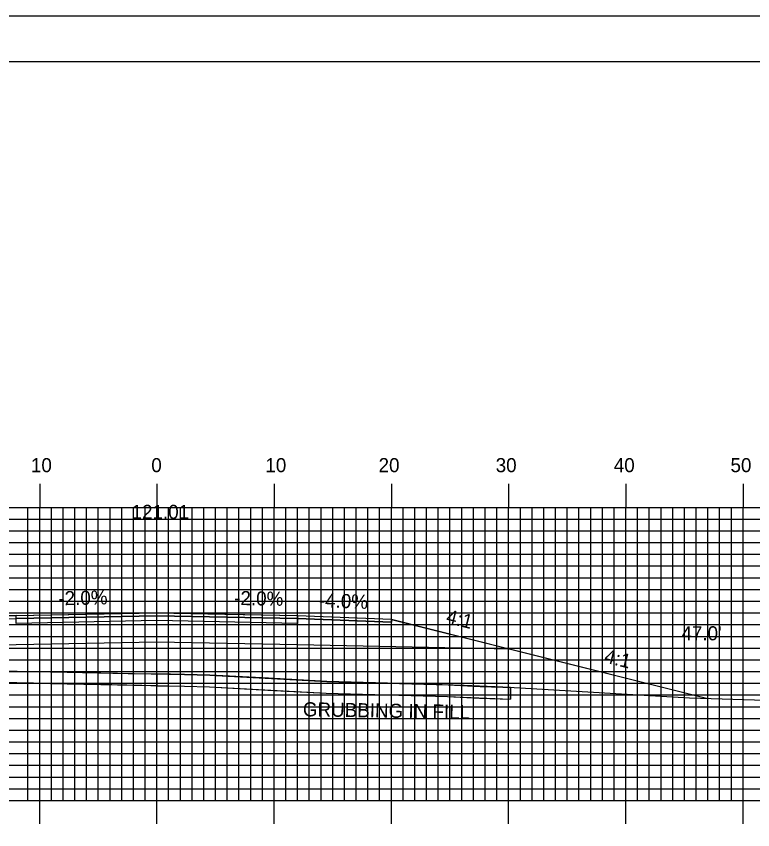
# Model space of a CAD drawing. Extents: x 1772022 to 1772366, y 442591 to 442811.
# Drawn here: x 1772176.1 to 1772238.9, y 442741.2 to 442810.5 of the extents above; entities that cross this region are included whole.
import ezdxf

# ---------------------------------------------------------------- set-up
doc = ezdxf.new("R2010")
doc.units = 0
for name, color, linetype in [('ANNOTATION', 7, 'Continuous'), ('BORDER', 7, 'Continuous'), ('D_Roadway_Centerline', 7, 'Continuous'), ('D_Roadway_Centerline_Text', 7, 'Continuous'), ('D_Roadway_Edge_Shoulder', 7, 'Continuous'), ('D_Roadway_Edge_TW', 7, 'Continuous'), ('D_Roadway_Pavement', 7, 'Continuous'), ('D_Roadway_SlopeLines', 7, 'Continuous'), ('D_Roadway_SubGrade', 7, 'Continuous'), ('D_Text_Standard', 7, 'Continuous'), ('GRUBBING IN FILL', 7, 'Continuous'), ('H_V ANNOTATION', 7, 'Continuous'), ('MAJOR', 7, 'Continuous'), ('MINOR', 7, 'Continuous'), ('PLOT BOUNDARY', 7, 'Continuous'), ('S_Roadway_Centerline', 7, 'Continuous')]:
    doc.layers.add(name, color=color, linetype=linetype)

msp = doc.modelspace()

# ---------------------------------------------------------------- linework, layer by layer
at = {"layer": 'BORDER'}
msp.add_lwpolyline([(1772038.494, 442596.665), (1772358.494, 442596.665), (1772358.494, 442806.665), (1772038.494, 442806.665)], close=True, dxfattribs=at)
at = {"layer": 'D_Roadway_Centerline'}
msp.add_lwpolyline([(1772154.321, 442755.673), (1772155.067, 442755.86), (1772156.093, 442756.116), (1772157.021, 442756.348), (1772157.919, 442756.572), (1772168.091, 442759.116), (1772168.093, 442759.116), (1772168.095, 442759.116), (1772176.094, 442759.436), (1772183.479, 442759.584), (1772188.09, 442759.676), (1772188.093, 442759.676), (1772193.883, 442759.56), (1772200.09, 442759.436), (1772200.093, 442759.436), (1772200.095, 442759.436), (1772208.094, 442759.116), (1772208.097, 442759.115), (1772218.268, 442756.572), (1772218.274, 442756.571), (1772235.086, 442752.368)], dxfattribs=at)
at = {"layer": 'D_Roadway_Edge_Shoulder'}
for points in [[(1772176.094, 442759.436), (1772168.093, 442759.116), (1772168.093, 442758.866), (1772176.094, 442759.186)], [(1772200.093, 442759.436), (1772208.094, 442759.116), (1772208.094, 442758.866), (1772200.093, 442759.186)]]:
    msp.add_lwpolyline(points, close=True, dxfattribs=at)
at = {"layer": 'D_Roadway_Edge_TW'}
msp.add_lwpolyline([(1772176.094, 442759.186), (1772176.094, 442759.436), (1772188.093, 442759.676), (1772200.093, 442759.436), (1772200.093, 442759.186), (1772188.093, 442759.426)], close=True, dxfattribs=at)
at = {"layer": 'D_Roadway_Pavement'}
msp.add_lwpolyline([(1772176.094, 442758.769), (1772176.094, 442759.186), (1772188.093, 442759.426), (1772200.093, 442759.186), (1772200.093, 442758.769), (1772188.093, 442759.009)], close=True, dxfattribs=at)
at = {"layer": 'D_Roadway_SlopeLines'}
msp.add_lwpolyline([(1772208.094, 442759.116), (1772218.268, 442756.572), (1772235.086, 442752.368)], dxfattribs=at)
at = {"layer": 'D_Roadway_SubGrade'}
msp.add_lwpolyline([(1772176.094, 442756.936), (1772157.919, 442756.572), (1772168.093, 442759.116), (1772168.093, 442758.866), (1772176.094, 442759.186), (1772188.093, 442759.426), (1772200.093, 442759.186), (1772208.094, 442758.866), (1772208.094, 442759.116), (1772218.268, 442756.572), (1772200.093, 442756.936), (1772188.093, 442757.176)], close=True, dxfattribs=at)
at = {"layer": 'GRUBBING IN FILL'}
msp.add_line((1772218.268, 442753.3), (1772218.268, 442752.3), dxfattribs=at)
msp.add_line((1772218.268, 442753.3), (1772218.268, 442752.3), dxfattribs=at)
for points in [[(1772157.919, 442755.405), (1772160.888, 442755.272), (1772165.211, 442755.078), (1772168.132, 442754.881), (1772170.426, 442754.81), (1772180.442, 442754.609), (1772185.641, 442754.505), (1772188.094, 442754.456), (1772188.094, 442753.455), (1772180.417, 442753.609), (1772170.4, 442753.81), (1772165.155, 442754.08), (1772157.919, 442754.404)], [(1772157.919, 442755.405), (1772160.888, 442755.272), (1772165.211, 442755.078), (1772168.132, 442754.881), (1772170.426, 442754.81), (1772180.442, 442754.609), (1772185.641, 442754.505), (1772188.094, 442754.456), (1772188.094, 442753.455), (1772180.417, 442753.609), (1772170.4, 442753.81), (1772165.155, 442754.08), (1772157.919, 442754.404)], [(1772188.094, 442753.455), (1772190.435, 442753.408), (1772192.574, 442753.345), (1772197.558, 442753.085), (1772202.543, 442752.825), (1772207.715, 442752.684), (1772212.888, 442752.544), (1772218.268, 442752.3), (1772218.268, 442753.3), (1772214.297, 442753.466), (1772207.756, 442753.684), (1772202.582, 442753.824), (1772197.598, 442754.084), (1772192.615, 442754.344), (1772190.459, 442754.408), (1772188.094, 442754.456)], [(1772188.094, 442753.455), (1772190.435, 442753.408), (1772192.574, 442753.345), (1772197.558, 442753.085), (1772202.543, 442752.825), (1772207.715, 442752.684), (1772212.888, 442752.544), (1772218.268, 442752.3), (1772218.268, 442753.3), (1772214.297, 442753.466), (1772207.756, 442753.684), (1772202.582, 442753.824), (1772197.598, 442754.084), (1772192.615, 442754.344), (1772190.459, 442754.408), (1772188.094, 442754.456)]]:
    msp.add_lwpolyline(points, close=True, dxfattribs=at)
msp.add_lwpolyline([(1772157.919, 442754.404), (1772165.155, 442754.08), (1772168.083, 442753.882), (1772170.4, 442753.81), (1772190.435, 442753.408), (1772192.574, 442753.345), (1772202.543, 442752.825), (1772212.888, 442752.544), (1772215.62, 442752.389), (1772218.268, 442752.3)], dxfattribs=at)
msp.add_lwpolyline([(1772157.919, 442754.404), (1772165.155, 442754.08), (1772168.083, 442753.882), (1772170.4, 442753.81), (1772190.435, 442753.408), (1772192.574, 442753.345), (1772202.543, 442752.825), (1772212.888, 442752.544), (1772215.62, 442752.389), (1772218.268, 442752.3)], dxfattribs=at)
at = {"layer": 'MAJOR'}
for p, q in [((1772178.094, 442770.669), (1772178.094, 442768.665)), ((1772188.094, 442770.669), (1772188.094, 442768.665)), ((1772198.094, 442770.669), (1772198.094, 442768.665)), ((1772208.094, 442770.669), (1772208.094, 442768.665)), ((1772218.094, 442770.669), (1772218.094, 442768.665)), ((1772228.094, 442770.669), (1772228.094, 442768.665)), ((1772238.094, 442770.669), (1772238.094, 442768.665)), ((1772048.094, 442768.665), (1772328.094, 442768.665)), ((1772048.094, 442768.665), (1772328.094, 442768.665)), ((1772178.094, 442743.665), (1772178.094, 442768.665)), ((1772188.094, 442743.665), (1772188.094, 442768.665)), ((1772198.094, 442743.665), (1772198.094, 442768.665)), ((1772208.094, 442743.665), (1772208.094, 442768.665)), ((1772218.094, 442743.665), (1772218.094, 442768.665)), ((1772228.094, 442743.665), (1772228.094, 442768.665)), ((1772238.094, 442743.665), (1772238.094, 442768.665)), ((1772048.094, 442763.665), (1772328.094, 442763.665)), ((1772048.094, 442758.665), (1772328.094, 442758.665)), ((1772048.094, 442753.665), (1772328.094, 442753.665)), ((1772048.094, 442748.665), (1772328.094, 442748.665)), ((1772048.094, 442743.665), (1772328.094, 442743.665)), ((1772048.094, 442743.665), (1772328.094, 442743.665)), ((1772178.094, 442741.661), (1772178.094, 442743.665)), ((1772188.094, 442741.661), (1772188.094, 442743.665)), ((1772198.094, 442741.661), (1772198.094, 442743.665)), ((1772208.094, 442741.661), (1772208.094, 442743.665)), ((1772218.094, 442741.661), (1772218.094, 442743.665)), ((1772228.094, 442741.661), (1772228.094, 442743.665)), ((1772238.094, 442741.661), (1772238.094, 442743.665))]:
    msp.add_line(p, q, dxfattribs=at)
at = {"layer": 'MINOR'}
for p, q in [((1772177.094, 442743.665), (1772177.094, 442768.665)), ((1772179.094, 442743.665), (1772179.094, 442768.665)), ((1772180.094, 442743.665), (1772180.094, 442768.665)), ((1772181.094, 442743.665), (1772181.094, 442768.665)), ((1772182.094, 442743.665), (1772182.094, 442768.665)), ((1772183.094, 442743.665), (1772183.094, 442768.665)), ((1772184.094, 442743.665), (1772184.094, 442768.665)), ((1772185.094, 442743.665), (1772185.094, 442768.665)), ((1772186.094, 442743.665), (1772186.094, 442768.665)), ((1772187.094, 442743.665), (1772187.094, 442768.665)), ((1772189.094, 442743.665), (1772189.094, 442768.665)), ((1772190.094, 442743.665), (1772190.094, 442768.665)), ((1772191.094, 442743.665), (1772191.094, 442768.665)), ((1772192.094, 442743.665), (1772192.094, 442768.665)), ((1772193.094, 442743.665), (1772193.094, 442768.665)), ((1772194.094, 442743.665), (1772194.094, 442768.665)), ((1772195.094, 442743.665), (1772195.094, 442768.665)), ((1772196.094, 442743.665), (1772196.094, 442768.665)), ((1772197.094, 442743.665), (1772197.094, 442768.665)), ((1772199.094, 442743.665), (1772199.094, 442768.665)), ((1772200.094, 442743.665), (1772200.094, 442768.665)), ((1772201.094, 442743.665), (1772201.094, 442768.665)), ((1772202.094, 442743.665), (1772202.094, 442768.665)), ((1772203.094, 442743.665), (1772203.094, 442768.665)), ((1772204.094, 442743.665), (1772204.094, 442768.665)), ((1772205.094, 442743.665), (1772205.094, 442768.665)), ((1772206.094, 442743.665), (1772206.094, 442768.665)), ((1772207.094, 442743.665), (1772207.094, 442768.665)), ((1772209.094, 442743.665), (1772209.094, 442768.665)), ((1772210.094, 442743.665), (1772210.094, 442768.665)), ((1772211.094, 442743.665), (1772211.094, 442768.665)), ((1772212.094, 442743.665), (1772212.094, 442768.665)), ((1772213.094, 442743.665), (1772213.094, 442768.665)), ((1772214.094, 442743.665), (1772214.094, 442768.665)), ((1772215.094, 442743.665), (1772215.094, 442768.665)), ((1772216.094, 442743.665), (1772216.094, 442768.665)), ((1772217.094, 442743.665), (1772217.094, 442768.665)), ((1772219.094, 442743.665), (1772219.094, 442768.665)), ((1772220.094, 442743.665), (1772220.094, 442768.665)), ((1772221.094, 442743.665), (1772221.094, 442768.665)), ((1772222.094, 442743.665), (1772222.094, 442768.665)), ((1772223.094, 442743.665), (1772223.094, 442768.665)), ((1772224.094, 442743.665), (1772224.094, 442768.665)), ((1772225.094, 442743.665), (1772225.094, 442768.665)), ((1772226.094, 442743.665), (1772226.094, 442768.665)), ((1772227.094, 442743.665), (1772227.094, 442768.665)), ((1772229.094, 442743.665), (1772229.094, 442768.665)), ((1772230.094, 442743.665), (1772230.094, 442768.665)), ((1772231.094, 442743.665), (1772231.094, 442768.665)), ((1772232.094, 442743.665), (1772232.094, 442768.665)), ((1772233.094, 442743.665), (1772233.094, 442768.665)), ((1772234.094, 442743.665), (1772234.094, 442768.665)), ((1772235.094, 442743.665), (1772235.094, 442768.665)), ((1772236.094, 442743.665), (1772236.094, 442768.665)), ((1772237.094, 442743.665), (1772237.094, 442768.665)), ((1772048.094, 442767.665), (1772328.094, 442767.665)), ((1772048.094, 442766.665), (1772328.094, 442766.665)), ((1772048.094, 442765.665), (1772328.094, 442765.665)), ((1772048.094, 442764.665), (1772328.094, 442764.665)), ((1772048.094, 442762.665), (1772328.094, 442762.665)), ((1772048.094, 442761.665), (1772328.094, 442761.665)), ((1772048.094, 442760.665), (1772328.094, 442760.665)), ((1772048.094, 442759.665), (1772328.094, 442759.665)), ((1772048.094, 442757.665), (1772328.094, 442757.665)), ((1772048.094, 442756.665), (1772328.094, 442756.665)), ((1772048.094, 442755.665), (1772328.094, 442755.665)), ((1772048.094, 442754.665), (1772328.094, 442754.665)), ((1772048.094, 442752.665), (1772328.094, 442752.665)), ((1772048.094, 442751.665), (1772328.094, 442751.665)), ((1772048.094, 442750.665), (1772328.094, 442750.665)), ((1772048.094, 442749.665), (1772328.094, 442749.665)), ((1772048.094, 442747.665), (1772328.094, 442747.665)), ((1772048.094, 442746.665), (1772328.094, 442746.665)), ((1772048.094, 442745.665), (1772328.094, 442745.665)), ((1772048.094, 442744.665), (1772328.094, 442744.665))]:
    msp.add_line(p, q, dxfattribs=at)
at = {"layer": 'PLOT BOUNDARY'}
msp.add_lwpolyline([(1772022.307, 442590.547), (1772362.307, 442590.547), (1772362.307, 442810.547), (1772022.307, 442810.547)], close=True, dxfattribs=at)
at = {"layer": 'S_Roadway_Centerline'}
msp.add_lwpolyline([(1772110.178, 442757.521), (1772130.932, 442756.345), (1772134.969, 442756.324), (1772144.642, 442756.221), (1772151.333, 442755.949), (1772156.564, 442755.465), (1772165.211, 442755.078), (1772168.132, 442754.881), (1772170.426, 442754.81), (1772190.459, 442754.408), (1772192.615, 442754.344), (1772202.582, 442753.824), (1772212.93, 442753.543), (1772215.665, 442753.389), (1772218.582, 442753.29), (1772233.532, 442752.414), (1772245.555, 442752.053)], dxfattribs=at)

# ---------------------------------------------------------------- texts
at = {"layer": 'ANNOTATION'}
for s, rotation, p in [('-2.0%', 1.14584, (1772179.698, 442760.309)), ('-2.0%', 358.85421, (1772194.673, 442760.345)), ('-4.0%', 357.70959, (1772201.886, 442760.166)), ('4:1', 345.96106, (1772212.688, 442758.829)), ('4:1', 345.96594, (1772226.186, 442755.455))]:
    msp.add_text(s, height=1.2, rotation=rotation, dxfattribs=at).set_placement(p)
at = {"layer": 'D_Roadway_Centerline'}
for s, p in [('C', (1772188.088, 442759.676)), ('L', (1772188.093, 442759.669))]:
    msp.add_text(s, height=0.0146, dxfattribs=at).set_placement(p)
at = {"layer": 'D_Roadway_Centerline_Text'}
msp.add_text('121.01', height=1.2, dxfattribs=at).set_placement((1772185.932, 442767.68))
at = {"layer": 'D_Text_Standard'}
msp.add_text("47.0'", height=1.2, dxfattribs=at).set_placement((1772232.837, 442757.325))
at = {"layer": 'GRUBBING IN FILL'}
msp.add_text('GRUBBING IN FILL', height=1.2, rotation=359.01917, dxfattribs=at).set_placement((1772200.535, 442750.853))
at = {"layer": 'H_V ANNOTATION'}
for s, p in [('10', (1772177.344, 442771.665)), ('0', (1772187.612, 442771.665)), ('10', (1772197.344, 442771.665)), ('20', (1772207.002, 442771.665)), ('30', (1772216.991, 442771.665)), ('40', (1772227.066, 442771.665)), ('50', (1772237.023, 442771.665))]:
    msp.add_text(s, height=1.2, dxfattribs=at).set_placement(p)

doc.saveas('drawing.dxf')
